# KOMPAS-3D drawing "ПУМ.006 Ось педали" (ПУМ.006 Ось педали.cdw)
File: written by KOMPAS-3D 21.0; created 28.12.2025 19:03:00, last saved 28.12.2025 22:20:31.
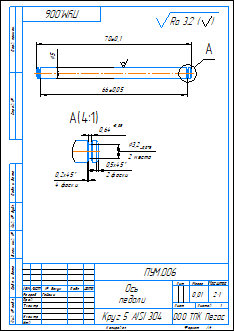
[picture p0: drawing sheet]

Sheet 1: A4, portrait

Document properties: Автор: Гузель; Организация: Марсель; Полное имя файла: C:\Users\User\Desktop\ПУ\ПУМ\Чертежи\ПУМ.006 Ось педали.cdw; Знак неуказанной шероховатости: 4; Параметр неуказанной шероховатости: Ra 3.2; Масса: 0.010643

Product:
- Part/product: ПУМ.006 Ось педали
    Масса: 0.010643
    Комментарий: Марсель

Title block, sheet 1: Наименование: Ось / педали; designation: ПУМ.006; Материал: Круг 5 AISI 304; Масса: 0,01; Количество листов документа: 1; organisation: ООО ТПК Пегас; Форматы листов документа: A4; stored path: C:\Users\Гузель\Desktop\ПУМ\Чертежи\ПУМ.006 Ось педали.cdw; Разработал: Гайсин

Views: Вид 1, Спереди, Выносной элемент 2, Выносной элемент А, Выносной элемент
Referenced files in C:\Users\Гузель\Desktop\ПУМ\: ПУМ.006 Ось педали.m3d
Referenced files in C:\Users\User\Desktop\ПУ\ПУМ\: ПУМ.006 Ось педали.m3d
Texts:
  ПУМ.006 Ось педали
  Ra 3.2
  Ra 3.2 ( )
Dimensions and other numbers on the sheet: 5; 70±0,1; 66±0,05; 6; 3,2; 2 места; 0,64; 0,5; 2 фаски; 0,2; 4 фаски; 2:1; 1; 0,01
